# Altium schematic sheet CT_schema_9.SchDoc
size 254 x 194 mm
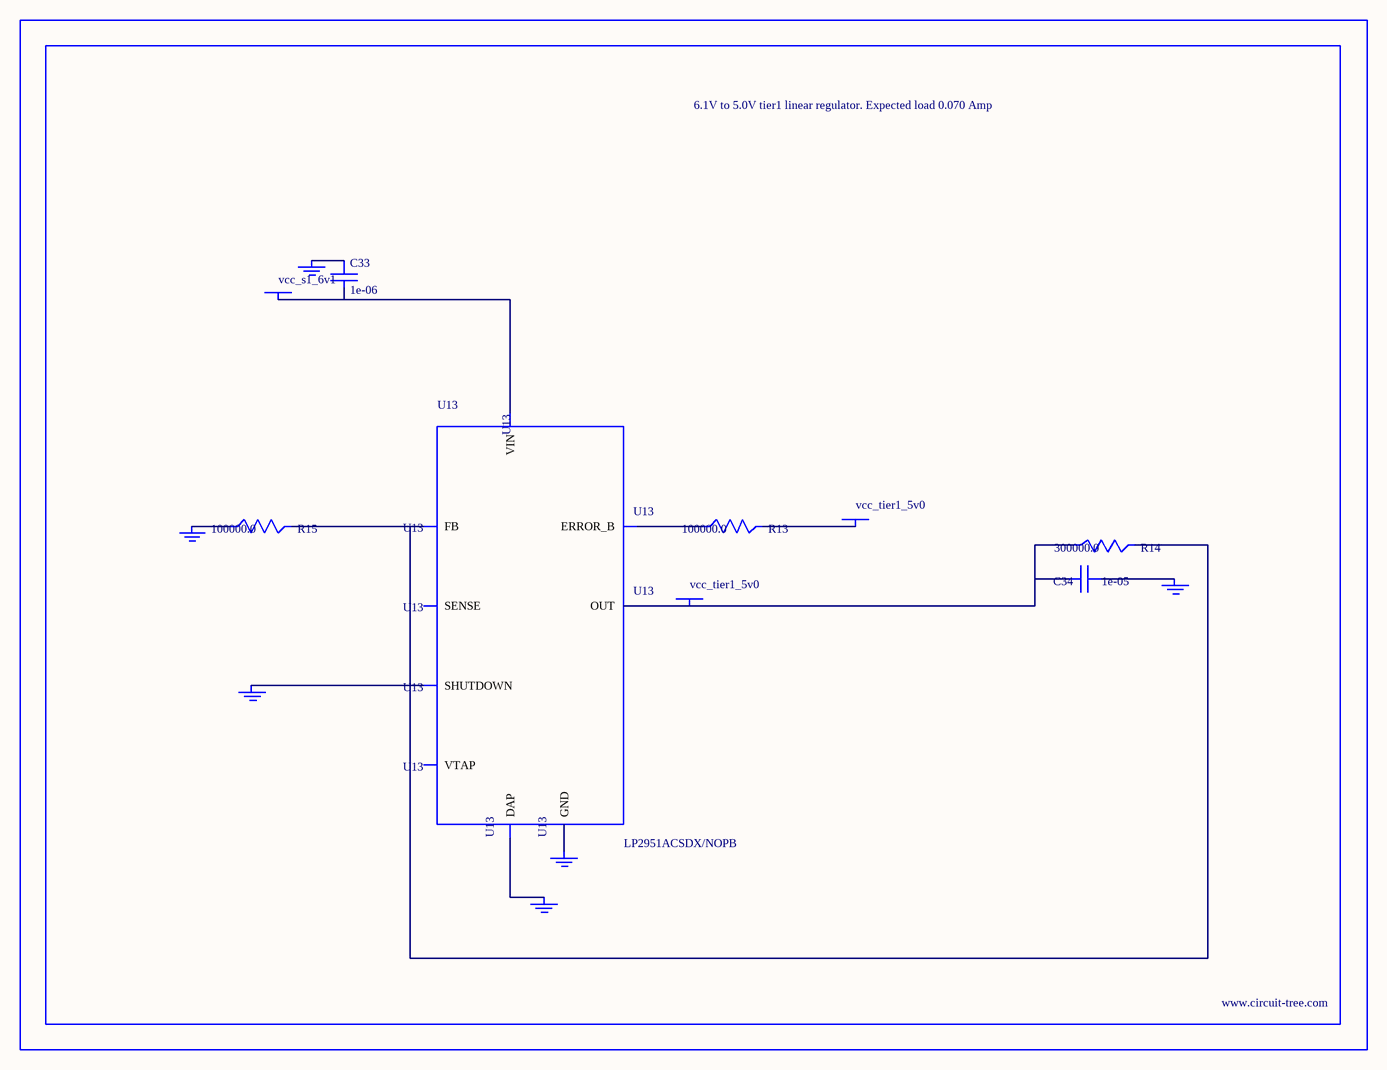
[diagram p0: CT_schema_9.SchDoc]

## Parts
BORDER8  (no value)
C33  1e-06  [C0603]
C34  1e-05  [C1210]
GND_INSTANCE_8_0  (no value)
GND_INSTANCE_8_1  (no value)
GND_INSTANCE_8_2  (no value)
GND_INSTANCE_8_3  (no value)
GND_INSTANCE_8_4  (no value)
GND_INSTANCE_8_5  (no value)
POWER_INSTANCE_8_0  vcc_tier1_5v0
POWER_INSTANCE_8_1  vcc_s1_6v1
POWER_INSTANCE_8_2  vcc_tier1_5v0
R13  100000.0  [R0603]
R14  300000.0  [R0603]
R15  100000.0  [R0603]
U13  LP2951ACSDX/NOPB  [WSON-8]

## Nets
NetC33_1: C33.1 GND_INSTANCE_8_3.0(GND)
NetC33_2: C33.2 POWER_INSTANCE_8_1.0(PWR) U13.8(VIN)
NetC34_1: C34.1 GND_INSTANCE_8_0.0(GND)
NetC34_2: C34.2 POWER_INSTANCE_8_2.0(PWR) R14.1 U13.1(OUT)
NetGND_INSTANCE_8_1_0: GND_INSTANCE_8_1.0(GND) U13.3(SHUTDOWN)
NetGND_INSTANCE_8_2_0: GND_INSTANCE_8_2.0(GND) R15.1
NetGND_INSTANCE_8_4_0: GND_INSTANCE_8_4.0(GND) U13.PAD(DAP)
NetGND_INSTANCE_8_5_0: GND_INSTANCE_8_5.0(GND) U13.4(GND)
NetPOWER_INSTANCE_8_0_0: POWER_INSTANCE_8_0.0(PWR) R13.2
NetR13_1: R13.1 U13.5(ERROR_B)
NetR14_2: R14.2 R15.2 U13.7(FB)

Not connected (* = marked no-connect by the designer): U13 2(SENSE) 6(VTAP)

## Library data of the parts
BORDER8 = BORDER_PAGE8
C33 = C0603C105K3RACTU
C34 = GRM32DR61E106MA12L
GND_INSTANCE_8_0-GND_INSTANCE_8_5 = GND
POWER_INSTANCE_8_0-POWER_INSTANCE_8_2 = PWR
R13 R15 = RC0603JR-07100KL
R14 = RC0603JR-07300KL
